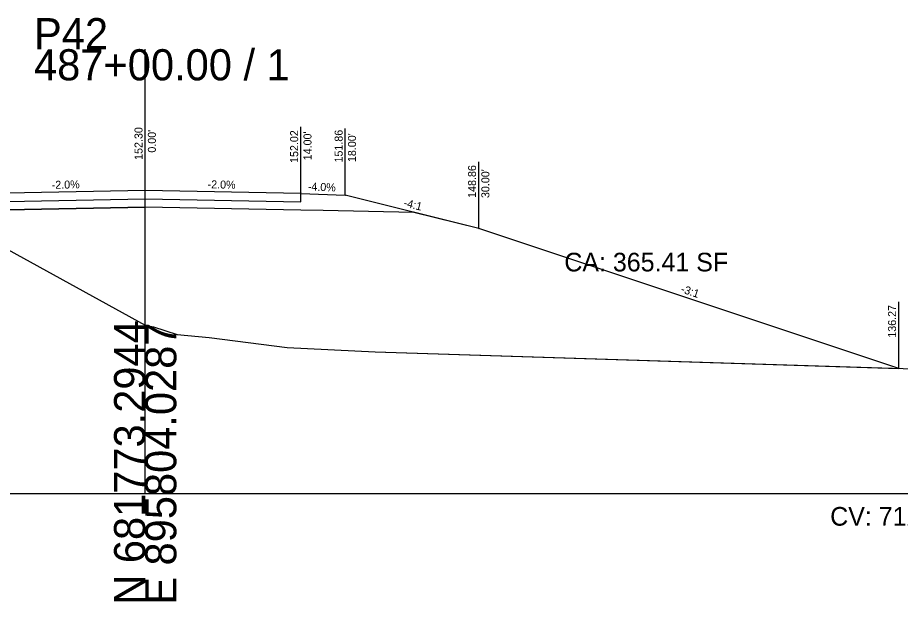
# Model space of a CAD drawing. Extents: x -26 to 4403, y -13 to 9578.
# Drawn here: x 3238.5 to 3317.9, y 8490.3 to 8542.8 of the extents above; entities that cross this region are included whole.
import ezdxf

# ---------------------------------------------------------------- set-up
doc = ezdxf.new("R2010")
doc.units = 0
for name, color, linetype in [('CONST_LV3', 7, 'Continuous'), ('CONST_PROF_LV1', 7, 'Continuous'), ('Default', 7, 'Continuous'), ('DTM CONTOURS_MAJOR', 7, 'Continuous'), ('DTM_CONTOURS_MINOR', 7, 'Continuous'), ('DTM_X_BOUNDARY', 7, 'Continuous'), ('DTM_X_GROUND', 7, 'Continuous'), ('X_PROFILES_1', 7, 'Continuous'), ('XS_CELL', 7, 'Continuous'), ('XS_M_SHAPES_EARTHWORK', 7, 'Continuous'), ('XS_P_ASPHALT', 7, 'Continuous'), ('XS_P_GROUND', 7, 'Continuous'), ('XS_P_SHOULDER', 7, 'Continuous'), ('XS_P_SUBGRADE_GRANULAR', 7, 'Continuous'), ('XS_P_TX_CLEARZONE', 7, 'Continuous'), ('XS_P_TX_FS_BS', 7, 'Continuous'), ('XS_SHEET_EW_TX_AREA', 7, 'Continuous'), ('XS_SHEET_EW_TX_VOLUME', 7, 'Continuous')]:
    doc.layers.add(name, color=color, linetype=linetype)

msp = doc.modelspace()

# ---------------------------------------------------------------- linework, layer by layer
at = {"layer": 'CONST_LV3'}
msp.add_lwpolyline([(3280, 8523.858), (3280, 8523.858), (3274.174, 8525.314)], dxfattribs=at)
at = {"layer": 'DTM_X_GROUND'}
msp.add_lwpolyline([(3153.808, 8513.95), (3170.909, 8514.966), (3177.153, 8518.209), (3197.118, 8527.209), (3198.789, 8527.5), (3201.713, 8527.882), (3210.312, 8528.066), (3213.777, 8528.123), (3216.864, 8528.039), (3224.572, 8527.826), (3225.877, 8527.605), (3229.562, 8526.928), (3236.992, 8522.323), (3249.998, 8515.154), (3250, 8515.153), (3250.751, 8515.018), (3252.885, 8514.328), (3255.752, 8514.055), (3262.783, 8513.146), (3270.679, 8512.757), (3325.754, 8511.013), (3363.759, 8510.776), (3378.096, 8510.765), (3400, 8511.068)], dxfattribs=at)
at = {"layer": 'XS_CELL'}
for p, q in [((3250, 8500), (3250, 8540)), ((3000, 8500), (3250, 8500)), ((3250, 8500), (3400, 8500))]:
    msp.add_line(p, q, dxfattribs=at)
at = {"layer": 'XS_M_SHAPES_EARTHWORK'}
msp.add_lwpolyline([(3231.967, 8525.437), (3236.992, 8522.323), (3249.998, 8515.154), (3250, 8515.153), (3250.751, 8515.018), (3252.885, 8514.328), (3255.752, 8514.055), (3262.783, 8513.146), (3270.679, 8512.757), (3317.781, 8511.266), (3280, 8523.858), (3274.174, 8525.314), (3266, 8525.478), (3264, 8525.518), (3250, 8525.798), (3236, 8525.518), (3234, 8525.478)], close=True, dxfattribs=at)
at = {"layer": 'XS_P_ASPHALT'}
msp.add_lwpolyline([(3236, 8527.018), (3236, 8527.018), (3236, 8526.268), (3236, 8526.268), (3236, 8526.268), (3250, 8526.548), (3264, 8526.268), (3264, 8526.268), (3264, 8526.268), (3264, 8527.018), (3264, 8527.018), (3250, 8527.298), (3236, 8527.018)], dxfattribs=at)
at = {"layer": 'XS_P_GROUND'}
msp.add_lwpolyline([(3317.781, 8511.266), (3317.78, 8511.266), (3280, 8523.858), (3280, 8523.858), (3268, 8526.858)], dxfattribs=at)
at = {"layer": 'XS_P_SHOULDER'}
msp.add_lwpolyline([(3264, 8527.018), (3268, 8526.858)], dxfattribs=at)
at = {"layer": 'XS_P_SUBGRADE_GRANULAR'}
for points in [[(3236, 8525.518), (3236, 8525.518), (3250, 8525.798)], [(3264, 8525.518), (3264, 8525.518), (3250, 8525.798)], [(3274.174, 8525.314), (3274.174, 8525.314), (3266, 8525.478), (3266, 8525.478), (3264, 8525.518)]]:
    msp.add_lwpolyline(points, dxfattribs=at)
at = {"layer": 'XS_P_TX_CLEARZONE'}
for p, q in [((3250, 8527.298), (3250, 8533.298)), ((3250, 8527.298), (3250, 8533.298)), ((3250, 8527.298), (3250, 8533.298)), ((3250, 8527.298), (3250, 8533.298)), ((3250, 8527.298), (3250, 8533.298)), ((3250, 8527.298), (3250, 8533.298)), ((3264, 8527.018), (3264, 8533.018)), ((3264, 8527.018), (3264, 8533.018)), ((3264, 8527.018), (3264, 8533.018)), ((3264, 8527.018), (3264, 8533.018)), ((3264, 8527.018), (3264, 8533.018)), ((3264, 8527.018), (3264, 8533.018)), ((3268, 8526.858), (3268, 8532.858)), ((3268, 8526.858), (3268, 8532.858)), ((3268, 8526.858), (3268, 8532.858)), ((3280, 8523.858), (3280, 8529.858)), ((3280, 8523.858), (3280, 8529.858)), ((3280, 8523.858), (3280, 8529.858)), ((3280, 8523.858), (3280, 8529.858)), ((3280, 8523.858), (3280, 8529.858)), ((3280, 8523.858), (3280, 8529.858)), ((3317.781, 8511.266), (3317.781, 8517.266)), ((3317.781, 8511.266), (3317.781, 8517.266)), ((3317.781, 8511.266), (3317.781, 8517.266)), ((3317.781, 8511.266), (3317.781, 8517.266)), ((3317.781, 8511.266), (3317.781, 8517.266)), ((3317.781, 8511.266), (3317.781, 8517.266)), ((3317.781, 8511.266), (3317.781, 8517.266)), ((3317.781, 8511.266), (3317.781, 8517.266)), ((3317.781, 8511.266), (3317.781, 8517.266))]:
    msp.add_line(p, q, dxfattribs=at)

# ---------------------------------------------------------------- texts
at = {"layer": 'CONST_PROF_LV1'}
msp.add_text('X', height=0.12, dxfattribs=at).set_placement((3279.961, 8523.798))
at = {"layer": 'Default'}
msp.add_text('X', height=0.12, dxfattribs=at).set_placement((3279.961, 8523.798))
at = {"layer": 'DTM CONTOURS_MAJOR'}
for p in [(3249.961, 8527.238), (3263.961, 8526.958)]:
    msp.add_text('X', height=0.12, dxfattribs=at).set_placement(p)
at = {"layer": 'DTM_CONTOURS_MINOR'}
msp.add_text('X', height=0.12, dxfattribs=at).set_placement((3317.741, 8511.206))
at = {"layer": 'DTM_X_BOUNDARY'}
msp.add_text('X', height=0.12, dxfattribs=at).set_placement((3267.961, 8526.798))
at = {"layer": 'X_PROFILES_1'}
msp.add_text('X', height=0.12, dxfattribs=at).set_placement((3317.741, 8511.206))
at = {"layer": 'XS_CELL'}
for s, p in [('P42', (3240, 8540)), ('487+00.00 / 1', (3240, 8537.2))]:
    msp.add_text(s, height=2.8, dxfattribs=at).set_placement(p)
for s, p in [('N 681773.2944', (3250, 8490)), ('E 895804.0287', (3252.8, 8490))]:
    msp.add_text(s, height=2.8, rotation=90, dxfattribs=at).set_placement(p)
at = {"layer": 'XS_P_TX_CLEARZONE'}
for s, p in [('152.30', (3249.76, 8530.04)), ('152.30', (3249.76, 8530.04)), ('152.30', (3249.76, 8530.04)), ('152.30', (3249.76, 8530.04)), ('152.30', (3249.76, 8530.04)), ('152.30', (3249.76, 8530.04)), ("0.00'", (3250.96, 8530.692)), ("0.00'", (3250.96, 8530.692)), ("0.00'", (3250.96, 8530.692)), ("0.00'", (3250.96, 8530.692)), ("0.00'", (3250.96, 8530.692)), ("0.00'", (3250.96, 8530.692)), ('152.02', (3263.76, 8529.765)), ('152.02', (3263.76, 8529.765)), ('152.02', (3263.76, 8529.765)), ('152.02', (3263.76, 8529.765)), ('152.02', (3263.76, 8529.765)), ('152.02', (3263.76, 8529.765)), ("14.00'", (3264.96, 8530.003)), ("14.00'", (3264.96, 8530.003)), ("14.00'", (3264.96, 8530.003)), ("14.00'", (3264.96, 8530.003)), ("14.00'", (3264.96, 8530.003)), ("14.00'", (3264.96, 8530.003)), ('151.86', (3267.76, 8529.804)), ('151.86', (3267.76, 8529.804)), ('151.86', (3267.76, 8529.804)), ("18.00'", (3268.96, 8529.843)), ("18.00'", (3268.96, 8529.843)), ("18.00'", (3268.96, 8529.843)), ('148.86', (3279.76, 8526.622)), ('148.86', (3279.76, 8526.622)), ('148.86', (3279.76, 8526.622)), ('148.86', (3279.76, 8526.622)), ('148.86', (3279.76, 8526.622)), ('148.86', (3279.76, 8526.622)), ("30.00'", (3280.96, 8526.605)), ("30.00'", (3280.96, 8526.605)), ("30.00'", (3280.96, 8526.605)), ("30.00'", (3280.96, 8526.605)), ("30.00'", (3280.96, 8526.605)), ("30.00'", (3280.96, 8526.605)), ('136.27', (3317.541, 8514.036)), ('136.27', (3317.541, 8514.036)), ('136.27', (3317.541, 8514.036)), ('136.27', (3317.541, 8514.036)), ('136.27', (3317.541, 8514.036)), ('136.27', (3317.541, 8514.036)), ('136.27', (3317.541, 8514.036)), ('136.27', (3317.541, 8514.036)), ('136.27', (3317.541, 8514.036))]:
    msp.add_text(s, height=0.72, rotation=90, dxfattribs=at).set_placement(p)
at = {"layer": 'XS_P_TX_FS_BS'}
for s, rotation, p in [('-2.0%', 1.14576, (3241.598, 8527.43)), ('-2.0%', 1.14576, (3241.598, 8527.43)), ('-2.0%', 1.14576, (3241.598, 8527.43)), ('-2.0%', 358.85424, (3255.61, 8527.486)), ('-2.0%', 358.85424, (3255.61, 8527.486)), ('-2.0%', 358.85424, (3255.61, 8527.486)), ('-4.0%', 357.70939, (3264.616, 8527.293)), ('-4.0%', 357.70939, (3264.616, 8527.293)), ('-4.0%', 357.70939, (3264.616, 8527.293)), ('-4:1', 345.96376, (3273.193, 8525.869)), ('-4:1', 345.96376, (3273.193, 8525.869)), ('-4:1', 345.96376, (3273.193, 8525.869)), ('-3:1', 341.56677, (3298.125, 8518.133)), ('-3:1', 341.56677, (3298.125, 8518.133)), ('-3:1', 341.56677, (3298.125, 8518.133))]:
    msp.add_text(s, height=0.72, rotation=rotation, dxfattribs=at).set_placement(p)
at = {"layer": 'XS_SHEET_EW_TX_AREA'}
msp.add_text('CA: 365.41 SF', height=1.68, dxfattribs=at).set_placement((3287.701, 8520))
at = {"layer": 'XS_SHEET_EW_TX_VOLUME'}
msp.add_text('CV: 712.16 CY', height=1.68, dxfattribs=at).set_placement((3311.615, 8497.12))

doc.saveas('drawing.dxf')
